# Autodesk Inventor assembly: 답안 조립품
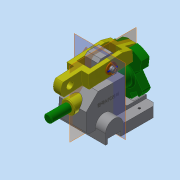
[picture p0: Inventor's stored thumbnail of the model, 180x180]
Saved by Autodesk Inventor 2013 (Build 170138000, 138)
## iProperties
Created: 2016-11
Part Number: 답안 조립품
Document SubType Name: Assembly
Designer: dgall
Author: dgall
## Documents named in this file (8)
- C:\Users\dgall\Desktop\461107V1020\답안 조립품.iam
- C:\Users\dgall\Desktop\461107V1020\본체.ipt
- C:\Users\dgall\Desktop\461107V1020\부시.ipt
- C:\Users\dgall\Desktop\461107V1020\분할축.ipt
- C:\Users\dgall\Desktop\461107V1020\클레비스핀.ipt
- C:\Users\dgall\Desktop\461107V1020\분할대.ipt
- C:\Users\dgall\Desktop\461107V1020\와셔.ipt
- C:\Users\dgall\Desktop\461107V1020\원통형핀.ipt
